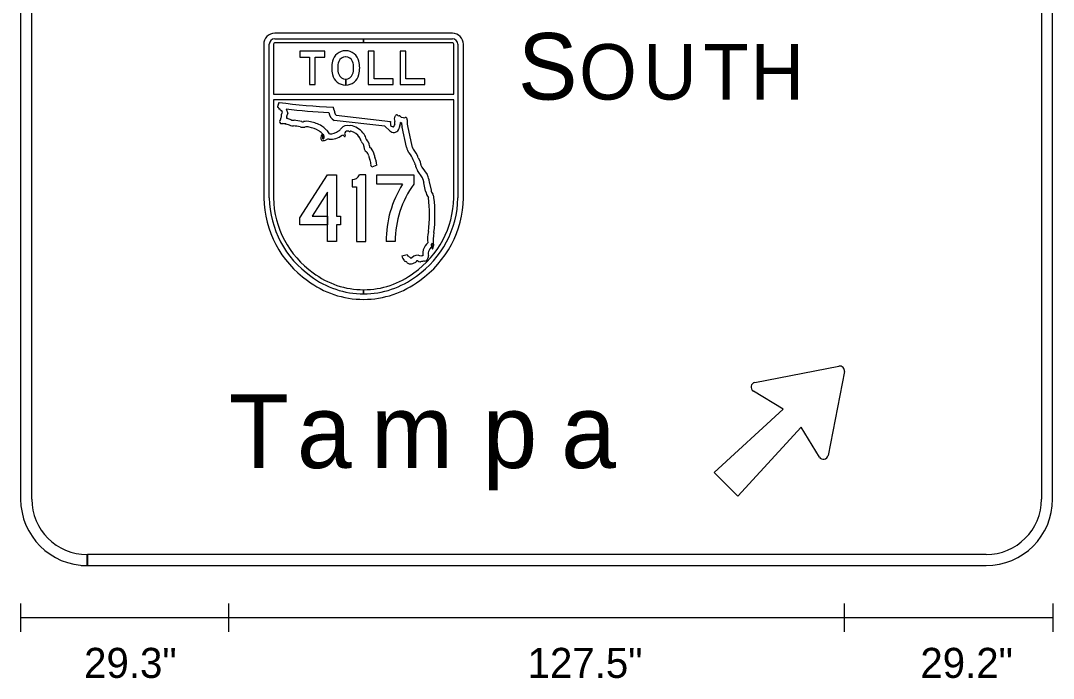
# Model space of a CAD drawing. Extents: x 10268312 to 10268472, y 2142583 to 2142688.
# Drawn here: x 10268433.86 to 10268458.09, y 2142612.8 to 2142628.24 of the extents above; entities that cross this region are included whole.
import ezdxf

# ---------------------------------------------------------------- set-up
doc = ezdxf.new("R2010")
doc.units = 0
doc.layers.add('GSDims', color=7, linetype='Continuous')
doc.layers.add('SignPanel', color=7, linetype='Continuous')

msp = doc.modelspace()

# ---------------------------------------------------------------- linework, layer by layer
at = {"layer": 'GSDims'}
for p, q in [((10268435.281, 2142615.451), (10268435.942, 2142615.451)), ((10268433.867, 2142613.893), (10268433.867, 2142614.555)), ((10268438.748, 2142613.893), (10268438.748, 2142614.554)), ((10268453.193, 2142613.893), (10268453.193, 2142614.554)), ((10268458.091, 2142613.893), (10268458.091, 2142614.554)), ((10268458.092, 2142614.224), (10268433.869, 2142614.224))]:
    msp.add_line(p, q, dxfattribs=at)
at = {"layer": 'SignPanel'}
for p, q in [((10268433.863, 2142634.19), (10268433.863, 2142617.008)), ((10268434.123, 2142617.008), (10268434.123, 2142634.19)), ((10268457.814, 2142634.19), (10268457.814, 2142617.008)), ((10268458.074, 2142617.008), (10268458.074, 2142634.19)), ((10268441.489, 2142626.868), (10268441.489, 2142626.727)), ((10268441.489, 2142626.727), (10268441.489, 2142626.868)), ((10268442.824, 2142624.397), (10268442.824, 2142624.397)), ((10268442.652, 2142623.054), (10268442.436, 2142623.054)), ((10268435.425, 2142615.446), (10268435.425, 2142615.707)), ((10268456.512, 2142615.707), (10268435.428, 2142615.707)), ((10268435.428, 2142615.707), (10268435.428, 2142615.446)), ((10268435.428, 2142615.446), (10268456.512, 2142615.446))]:
    msp.add_line(p, q, dxfattribs=at)
for points in [[(10268443.992, 2142627.942), (10268439.826, 2142627.942)], [(10268439.566, 2142627.682), (10268439.566, 2142624.076)], [(10268439.696, 2142624.077), (10268439.696, 2142627.682)], [(10268439.794, 2142627.682), (10268439.794, 2142626.511), (10268444.024, 2142626.511), (10268444.024, 2142627.682)], [(10268439.826, 2142627.812), (10268441.909, 2142627.812), (10268441.909, 2142627.715), (10268439.826, 2142627.715)], [(10268443.992, 2142627.715), (10268441.909, 2142627.715), (10268441.909, 2142627.812), (10268443.992, 2142627.812)], [(10268444.122, 2142627.682), (10268444.122, 2142624.077)], [(10268444.252, 2142624.076), (10268444.252, 2142627.682)], [(10268444.024, 2142624.078), (10268444.024, 2142626.38), (10268439.794, 2142626.38), (10268439.794, 2142624.078)], [(10268439.96, 2142626.139), (10268439.955, 2142626.151)], [(10268440.089, 2142626.165), (10268440.128, 2142626.062)], [(10268441.263, 2142626.021), (10268442.541, 2142625.873)], [(10268442.794, 2142625.975), (10268442.835, 2142625.961)], [(10268440.074, 2142625.811), (10268440.07, 2142625.812)], [(10268440.08, 2142625.817), (10268440.077, 2142625.813)], [(10268442.523, 2142625.653), (10268442.41, 2142625.757), (10268441.217, 2142625.896)], [(10268442.606, 2142625.754), (10268442.614, 2142625.746)], [(10268442.799, 2142625.836), (10268442.776, 2142625.844)], [(10268442.914, 2142625.269), (10268442.815, 2142625.737)], [(10268442.942, 2142625.769), (10268443.042, 2142625.294)], [(10268443.118, 2142624.876), (10268443.069, 2142624.968)], [(10268443.19, 2142625.018), (10268443.236, 2142624.933)], [(10268442.222, 2142624.848), (10268442.101, 2142624.801)], [(10268443.292, 2142624.55), (10268443.175, 2142624.719)], [(10268443.279, 2142624.798), (10268443.4, 2142624.623)], [(10268441.638, 2142624.507), (10268441.638, 2142624.335), (10268441.746, 2142624.335)], [(10268441.746, 2142624.335), (10268441.746, 2142623.054), (10268441.961, 2142623.054), (10268441.961, 2142624.616), (10268441.815, 2142624.616)], [(10268442.824, 2142624.397), (10268442.223, 2142624.397), (10268442.223, 2142624.616), (10268443.085, 2142624.616), (10268443.085, 2142624.397)], [(10268443.364, 2142624.233), (10268443.32, 2142624.428)], [(10268443.447, 2142624.458), (10268443.492, 2142624.256)], [(10268442.806, 2142622.719), (10268442.934, 2142622.745)], [(10268443.412, 2142622.661), (10268443.403, 2142622.631)], [(10268441.909, 2142621.825), (10268441.909, 2142621.922)], [(10268441.909, 2142621.922), (10268441.909, 2142621.825)], [(10268441.909, 2142621.825), (10268441.909, 2142621.825)], [(10268451.091, 2142619.748), (10268453.059, 2142620.129)], [(10268453.189, 2142619.999), (10268452.807, 2142618.031)], [(10268452.604, 2142617.995), (10268452.175, 2142618.694), (10268450.692, 2142617.075), (10268450.134, 2142617.632), (10268451.754, 2142619.116), (10268451.054, 2142619.544)]]:
    msp.add_lwpolyline(points, dxfattribs=at)
for points in [[(10268440.415, 2142627.383), (10268440.637, 2142627.383), (10268440.637, 2142626.738), (10268440.774, 2142626.738), (10268440.774, 2142627.383), (10268440.997, 2142627.383), (10268440.997, 2142627.519), (10268440.415, 2142627.519)], [(10268442.602, 2142626.738), (10268442.602, 2142626.875), (10268442.156, 2142626.875), (10268442.156, 2142627.519), (10268442.02, 2142627.519), (10268442.02, 2142626.738)], [(10268443.347, 2142626.738), (10268443.347, 2142626.875), (10268442.902, 2142626.875), (10268442.902, 2142627.519), (10268442.766, 2142627.519), (10268442.766, 2142626.738)], [(10268440.415, 2142623.446), (10268440.415, 2142623.606), (10268441.061, 2142624.616), (10268441.277, 2142624.616), (10268441.277, 2142623.649), (10268441.369, 2142623.649), (10268441.369, 2142623.446), (10268441.277, 2142623.446), (10268441.277, 2142623.054), (10268441.061, 2142623.054), (10268441.061, 2142624.215), (10268440.699, 2142623.649), (10268441.061, 2142623.649), (10268441.061, 2142623.446)]]:
    msp.add_lwpolyline(points, close=True, dxfattribs=at)
for centre, radius, start, end in [((10268439.826, 2142627.682), 0.26, 90, 180), ((10268443.992, 2142627.682), 0.26, 0, 90), ((10268439.826, 2142627.682), 0.13, 90, 180), ((10268439.826, 2142627.682), 0.0325, 90, 180), ((10268443.992, 2142627.682), 0.13, 0, 90), ((10268443.992, 2142627.682), 0.0325, 0, 90), ((10268441.484, 2142627.216), 0.314, 89.1819, 167.5018), ((10268441.49, 2142627.213), 0.178, 90.4555, 158.2948), ((10268441.493, 2142627.216), 0.314, 12.4982, 90.8181), ((10268441.487, 2142627.213), 0.178, 21.7052, 89.5445), ((10268441.932, 2142627.125), 0.772, 168.0806, 179.7176), ((10268441.779, 2142627.13), 0.478, 161.9125, 180.1219), ((10268441.198, 2142627.13), 0.478, 359.8781, 18.0875), ((10268441.045, 2142627.125), 0.772, 0.2824, 11.9194), ((10268441.932, 2142627.133), 0.772, 180.2824, 191.9194), ((10268441.484, 2142627.041), 0.314, 192.4982, 270.8181), ((10268441.779, 2142627.128), 0.478, 179.8781, 198.0875), ((10268441.49, 2142627.045), 0.178, 201.7052, 269.5445), ((10268441.487, 2142627.045), 0.178, 270.4681, 338.2948), ((10268441.493, 2142627.041), 0.314, 269.189, 347.5018), ((10268441.198, 2142627.128), 0.478, 341.9125, 0.1219), ((10268441.045, 2142627.133), 0.772, 348.0806, 359.7176), ((10268441.673, 2142625.514), 1.922, 157.1601, 158.4432), ((10268439.895, 2142626.217), 0.00879, 165.5291, 281.9694), ((10268439.899, 2142626.196), 0.0134, 28.407, 100.8351), ((10268439.805, 2142626.33), 0.12, 324.0903, 353.458), ((10268439.716, 2142626.062), 0.24, 24.7872, 35.7021), ((10268441.809, 2142641.115), 14.918, 262.7434, 267.6405), ((10268441.145, 2142626.183), 0.0559, 1.3749, 27.9458), ((10268441.265, 2142626.184), 0.0645, 179.3658, 215.5418), ((10268439.94, 2142626.164), 0.00687, 194.4693, 288.162), ((10268439.946, 2142626.149), 0.00942, 13.6845, 112.751), ((10268439.94, 2142625.943), 0.0293, 303.163, 9.1931), ((10268439.973, 2142626.143), 0.0138, 195.3224, 266.8181), ((10268440.437, 2142625.934), 0.468, 159.2675, 178.3646), ((10268439.966, 2142626.094), 0.0356, 28.9186, 79.1899), ((10268439.984, 2142626.103), 0.0156, 347.7695, 32.1923), ((10268441.809, 2142641.115), 15.048, 263.4397, 267.2795), ((10268440.437, 2142625.934), 0.338, 167.5112, 177.2509), ((10268439.94, 2142625.943), 0.159, 1.7758, 2.7093), ((10268440.082, 2142625.816), 0.132, 69.4831, 82.506), ((10268439.966, 2142626.094), 0.166, 328.3042, 348.8285), ((10268441.014, 2142628.24), 2.464, 248.9396, 251.3539), ((10268441.339, 2142626.109), 0.246, 186.0226, 240.1771), ((10268441.194, 2142626.122), 0.0306, 346.084, 50.7997), ((10268441.339, 2142626.109), 0.116, 177.0594, 229.2876), ((10268442.794, 2142625.935), 0.165, 157.7486, 202.5665), ((10268442.648, 2142626.008), 0.0127, 235.7363, 356.0329), ((10268442.697, 2142625.995), 0.0382, 115.3156, 161.8784), ((10268442.686, 2142626.015), 0.0158, 44.0046, 110.3969), ((10268442.811, 2142626.133), 0.156, 223.5643, 238.6353), ((10268442.735, 2142626.013), 0.0145, 247.007, 304.0945), ((10268442.75, 2142625.99), 0.0126, 56.0813, 120.6469), ((10268442.722, 2142625.939), 0.0717, 32.1927, 60.4948), ((10268442.772, 2142625.857), 0.12, 79.2817, 84.9051), ((10268442.853, 2142626.054), 0.0943, 258.6945, 288.9306), ((10268442.892, 2142625.923), 0.042, 345.9231, 100.3442), ((10268439.992, 2142625.874), 0.0567, 129.0954, 238.4286), ((10268440.004, 2142625.967), 0.147, 253.2596, 272.864), ((10268440.003, 2142625.533), 0.287, 76.4851, 88.2197), ((10268440.075, 2142625.814), 0.0026, 252.4967, 338.0613), ((10268440.082, 2142625.816), 0.00215, 73.12, 163.7815), ((10268441.014, 2142628.24), 2.594, 248.9638, 251.5032), ((10268440.285, 2142626.177), 0.409, 256.7183, 267.4737), ((10268440.285, 2142626.177), 0.278, 257.8372, 268.5604), ((10268439.985, 2142623.701), 2.087, 77.9815, 82.2503), ((10268440.012, 2142623.876), 2.04, 77.421, 82.517), ((10268440.479, 2142625.946), 0.212, 253.7173, 283.3082), ((10268440.479, 2142625.946), 0.0822, 253.7173, 284.0944), ((10268440.573, 2142625.527), 0.348, 75.2933, 102.1802), ((10268440.573, 2142625.527), 0.217, 74.3032, 101.8022), ((10268440.493, 2142625.01), 0.739, 60.4723, 79.2121), ((10268440.493, 2142625.01), 0.87, 60.1681, 78.8728), ((10268440.653, 2142625.347), 0.499, 43.098, 56.8309), ((10268441.257, 2142625.951), 0.356, 227.6878, 233.2173), ((10268441.259, 2142625.766), 0.134, 298.9664, 333.7554), ((10268441.532, 2142625.576), 0.201, 76.9537, 139.3646), ((10268441.606, 2142625.625), 0.149, 73.2041, 100.9837), ((10268441.49, 2142625.262), 0.53, 35.5557, 72.5764), ((10268442.583, 2142625.864), 0.0429, 168.2277, 203.6736), ((10268442.139, 2142625.783), 0.41, 1.0641, 8.9029), ((10268442.559, 2142625.77), 0.0127, 153.6943, 261.3292), ((10268442.511, 2142625.787), 0.0379, 342.1046, 5.5258), ((10268442.582, 2142625.98), 0.224, 263.5113, 273.8192), ((10268442.597, 2142625.743), 0.0141, 52.5269, 90.617), ((10268442.616, 2142625.748), 0.00283, 214.5297, 323.133), ((10268442.604, 2142625.755), 0.0169, 329.218, 356.8711), ((10268442.789, 2142625.731), 0.17, 152.3853, 172.0794), ((10268442.554, 2142625.845), 0.0912, 337.2402, 17.1915), ((10268442.604, 2142625.755), 0.147, 327.5985, 353.2264), ((10268442.789, 2142625.731), 0.0397, 148.6124, 169.8671), ((10268442.554, 2142625.845), 0.221, 335.0602, 359.8114), ((10268443.251, 2142625.861), 0.453, 183.1424, 195.902), ((10268443.251, 2142625.861), 0.323, 170.7154, 196.6283), ((10268440.653, 2142625.347), 0.369, 42.4108, 56.2622), ((10268441.025, 2142625.489), 0.119, 147.3117, 208.0117), ((10268441.257, 2142625.951), 0.486, 226.9799, 233.2376), ((10268440.931, 2142625.553), 0.00649, 42.7018, 175.2249), ((10268440.928, 2142625.541), 0.0186, 332.7536, 66.4691), ((10268441.042, 2142625.505), 0.101, 164.6264, 198.1355), ((10268440.961, 2142625.482), 0.0169, 210.7489, 325.0107), ((10268440.878, 2142625.821), 0.409, 279.5651, 292.434), ((10268440.941, 2142625.528), 0.0417, 351.1974, 53.4244), ((10268440.873, 2142625.513), 0.11, 338.4616, 4.2264), ((10268441.08, 2142625.352), 0.102, 79.7567, 117.0225), ((10268440.925, 2142625.51), 0.196, 21.6764, 52.5951), ((10268441.128, 2142625.902), 0.45, 266.2503, 307.7859), ((10268441.128, 2142625.902), 0.32, 266.2503, 307.7859), ((10268441.416, 2142625.511), 0.0368, 37.3199, 110.3481), ((10268441.483, 2142625.557), 0.0442, 212.4117, 239.272), ((10268441.468, 2142625.528), 0.0118, 228.4958, 341.3555), ((10268441.492, 2142625.589), 0.0291, 152.1797, 225.8444), ((10268441.532, 2142625.576), 0.0711, 67.674, 157.9537), ((10268441.448, 2142625.541), 0.0351, 331.5537, 49.3579), ((10268441.578, 2142625.658), 0.0251, 220.9479, 299.1324), ((10268441.606, 2142625.625), 0.019, 74.4586, 145.9267), ((10268441.49, 2142625.262), 0.4, 36.2481, 72.4315), ((10268441.456, 2142625.288), 0.414, 16.5783, 30.6264), ((10268441.456, 2142625.288), 0.544, 18.1844, 31.298), ((10268441.998, 2142625.476), 0.0313, 216.5526, 229.0303), ((10268441.815, 2142625.291), 0.229, 2.3462, 44.886), ((10268442.616, 2142625.748), 0.133, 225.5626, 327.298), ((10268440.942, 2142625.441), 0.0235, 198.3267, 279.0855), ((10268441.998, 2142625.476), 0.161, 205.822, 226.4387), ((10268441.815, 2142625.291), 0.0989, 0.3249, 43.6616), ((10268442.346, 2142625.336), 0.434, 185.834, 196.527), ((10268442.017, 2142625.242), 0.0921, 198.8094, 237.9225), ((10268442.346, 2142625.336), 0.304, 186.6712, 193.4993), ((10268441.869, 2142625.031), 0.296, 7.7551, 52.1923), ((10268443.184, 2142625.316), 0.274, 189.9178, 222.3355), ((10268443.184, 2142625.316), 0.144, 189.1367, 223.0108), ((10268442.648, 2142624.848), 0.568, 17.4036, 40.6855), ((10268441.869, 2142625.031), 0.166, 10.35, 53.3023), ((10268442.25, 2142625.067), 0.217, 181.6774, 206.2514), ((10268441.715, 2142624.81), 0.376, 15.4646, 25.4026), ((10268442.25, 2142625.067), 0.0873, 177.5076, 206.6985), ((10268441.715, 2142624.81), 0.506, 15.9958, 25.5439), ((10268442.648, 2142624.848), 0.438, 15.9174, 40.4167), ((10268442.112, 2142624.851), 0.0389, 157.2285, 204.3206), ((10268442.022, 2142624.889), 0.0588, 337.0801, 20.7155), ((10268442.022, 2142624.771), 0.0843, 20.8466, 49.4435), ((10268442.022, 2142624.889), 0.189, 355.1883, 18.52), ((10268442.022, 2142624.771), 0.214, 20.8466, 28.47), ((10268443.062, 2142624.854), 0.0606, 2.7263, 22.0432), ((10268443.359, 2142624.868), 0.236, 182.8439, 219.0546), ((10268443.062, 2142624.854), 0.191, 2.7846, 24.6707), ((10268443.359, 2142624.868), 0.106, 182.8834, 221.2348), ((10268443.212, 2142624.497), 0.0958, 4.1901, 33.4211), ((10268443.805, 2142624.544), 0.499, 184.5678, 193.4024), ((10268443.212, 2142624.497), 0.226, 4.3296, 33.8421), ((10268443.805, 2142624.544), 0.369, 184.6156, 193.5073), ((10268443.67, 2142624.279), 0.309, 188.6513, 218.6552), ((10268443.67, 2142624.279), 0.179, 187.3578, 219.0561), ((10268441.991, 2142624.118), 2.425, 181.0043, 234.7824), ((10268441.991, 2142624.118), 2.295, 181.0324, 234.8374), ((10268441.991, 2142624.118), 2.197, 181.0551, 234.883), ((10268441.827, 2142624.118), 2.197, 305.117, 358.9449), ((10268441.827, 2142624.118), 2.295, 305.1626, 358.9676), ((10268441.827, 2142624.118), 2.425, 305.2176, 358.9957), ((10268440.111, 2142623.676), 3.343, 353.2894, 7.0511), ((10268443.44, 2142624.088), 0.119, 358.1697, 40.7248), ((10268440.111, 2142623.676), 3.473, 353.1751, 6.7627), ((10268444.286, 2142623.095), 0.876, 167.4851, 184.9687), ((10268444.286, 2142623.095), 0.746, 167.0031, 190.1775), ((10268443.506, 2142622.899), 0.152, 127.78, 141.8214), ((10268443.546, 2142622.768), 0.25, 171.6034, 189.666), ((10268443.677, 2142622.742), 0.384, 139.1354, 170.6741), ((10268443.546, 2142622.768), 0.12, 172.0665, 198.8984), ((10268443.677, 2142622.742), 0.254, 138.1959, 170.4168), ((10268443.506, 2142622.899), 0.022, 120.7327, 146.8996), ((10268443.482, 2142622.932), 0.0195, 313.0663, 1.0356), ((10268443.606, 2142622.943), 0.105, 170.3514, 185.4188), ((10268442.117, 2142623.057), 1.388, 356.0203, 357.2657), ((10268443.54, 2142622.986), 0.0356, 127.6584, 172.8608), ((10268443.528, 2142622.898), 0.0153, 134.2076, 212.14), ((10268443.524, 2142622.892), 0.00945, 196.4727, 335.0579), ((10268443.469, 2142622.94), 0.0569, 327.0791, 0.5478), ((10268443.521, 2142623.009), 0.00582, 46.9365, 126.8217), ((10268443.471, 2142622.968), 0.0711, 23.2755, 40.0825), ((10268443.704, 2142622.925), 0.178, 159.7748, 175.1486), ((10268443.436, 2142622.951), 0.115, 326.8479, 355.1084), ((10268443.517, 2142622.99), 0.0202, 350.3295, 17.1364), ((10268443.469, 2142622.956), 0.0835, 349.8268, 5.1189), ((10268443.047, 2142622.769), 0.246, 191.6966, 222.0004), ((10268442.911, 2142622.658), 0.0711, 229.3982, 259.6246), ((10268442.883, 2142622.538), 0.0521, 32.3456, 73.6159), ((10268442.957, 2142622.572), 0.0308, 191.348, 254.6229), ((10268443.047, 2142622.769), 0.116, 191.6966, 211.3604), ((10268442.883, 2142622.538), 0.182, 42.6959, 69.0497), ((10268443.009, 2142622.661), 0.132, 243.3233, 293.7616), ((10268442.625, 2142623.682), 1.093, 291.0408, 292.5202), ((10268443.168, 2142622.575), 0.157, 60.4014, 141.9928), ((10268442.625, 2142623.682), 1.223, 290.9436, 294.6157), ((10268443.132, 2142622.578), 0.00883, 287.7304, 347.8777), ((10268443.168, 2142622.575), 0.0273, 59.3592, 177.5624), ((10268443.299, 2142622.811), 0.243, 240.9778, 254.1456), ((10268443.24, 2142622.62), 0.0434, 260.3414, 279.6586), ((10268443.299, 2142622.811), 0.113, 241.3901, 243.296), ((10268443.504, 2142621.364), 1.24, 97.769, 101.9213), ((10268443.504, 2142621.364), 1.37, 98.7313, 100.7273), ((10268443.498, 2142622.62), 0.225, 151.9345, 153.926), ((10268443.28, 2142622.816), 0.23, 284.2379, 299.9306), ((10268443.376, 2142622.638), 0.0283, 311.1053, 345.7508), ((10268443.498, 2142622.62), 0.0949, 137.4164, 154.489), ((10268443.387, 2142622.71), 0.0489, 327.0792, 21.8007), ((10268441.909, 2142623.875), 1.953, 232.735, 270), ((10268441.909, 2142623.875), 1.953, 270.0015, 307.265), ((10268441.909, 2142623.875), 2.18, 232.8475, 269.9993), ((10268441.909, 2142623.875), 2.05, 232.7862, 270), ((10268441.909, 2142623.875), 2.05, 270.0015, 307.2138), ((10268441.909, 2142623.875), 2.18, 270.0007, 307.1525), ((10268453.08, 2142620.02), 0.111, 349.0223, 100.9777), ((10268451.112, 2142619.639), 0.111, 100.9777, 238.5155), ((10268452.698, 2142618.052), 0.111, 211.4845, 349.0223), ((10268435.425, 2142617.008), 1.562, 180, 270), ((10268435.425, 2142617.008), 1.302, 180, 270), ((10268456.512, 2142617.008), 1.562, 270, 0), ((10268456.512, 2142617.008), 1.302, 270, 0)]:
    msp.add_arc(centre, radius, start, end, dxfattribs=at)
for centre, major_axis, start_param, end_param in [((10268441.638, 2142624.709), (0, 0.202), 3.141593, 4.23517), ((10268444.89, 2142623.054), (0, 2.491), 1.001327, 1.570796), ((10268444.89, 2142623.054), (0, 2.273), 0.938417, 1.570796)]:
    msp.add_ellipse(centre, major_axis=major_axis, ratio=0.985, start_param=start_param, end_param=end_param, dxfattribs=at)

# ---------------------------------------------------------------- texts
at = {"layer": 'GSDims'}
for s, p in [('29.3"', (10268435.352, 2142612.811)), ('127.5"', (10268445.757, 2142612.811)), ('29.2"', (10268454.972, 2142612.811))]:
    msp.add_text(s, height=0.7056, dxfattribs=at).set_placement(p)
at = {"layer": 'SignPanel'}
for s, height, p in [('S', 1.562, (10268445.532, 2142626.385)), ('O', 1.302, (10268446.965, 2142626.385)), ('U', 1.302, (10268448.467, 2142626.385)), ('T', 1.302, (10268449.882, 2142626.385)), ('H', 1.302, (10268450.987, 2142626.385)), ('T', 1.731, (10268438.746, 2142617.737)), ('a', 1.731, (10268440.344, 2142617.737)), ('m', 1.731, (10268442.079, 2142617.737)), ('p', 1.731, (10268444.698, 2142617.737)), ('a', 1.731, (10268446.542, 2142617.737))]:
    msp.add_text(s, height=height, rotation=0, dxfattribs=at).set_placement(p)

doc.saveas('drawing.dxf')
